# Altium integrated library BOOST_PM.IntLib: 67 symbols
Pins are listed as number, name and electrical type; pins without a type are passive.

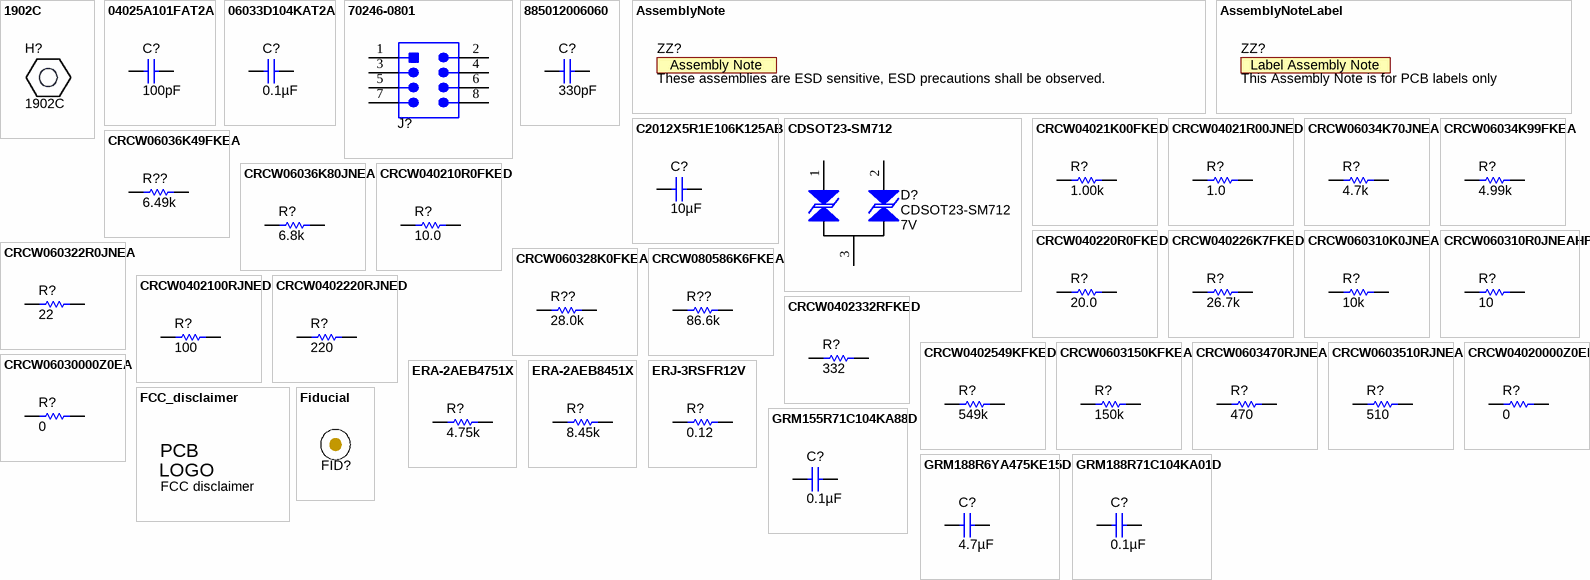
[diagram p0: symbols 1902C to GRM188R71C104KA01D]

## 1902C
designator H?
Standoff, Hex, 0.5"L #4-40 Nylon; Manufacturer: Keystone; CompType: Hardware
footprint Keystone_1902C

## 04025A101FAT2A
designator C?  ValueDisplayed: 100pF  (hidden comment: 04025A101FAT2A)
CAP, CERM, 100 pF, 50 V, +/- 1%, C0G/NP0, 0402; Manufacturer: AVX; Polarized: N; CompType: Capacitor; Value: 100pF; U/M: EA; Cap_F: 0.0000000001; Tolerance_%: 1; Value1: Unknown; VDC_V: 50; Value2: 50V; TaMin_C: -55; TaMax_C: 125; Cap_Case: 0402; SizeArea_mm2: 0.5; SizeAreaWB_mm2: 3; SizeZ_mm: 0.6; AEC Category: Q200
signal-integrity model Cap
simulation model Cap
footprint 0402
footprint 0402M
footprint 0402L
footprint 0402S
pins: 1, 2

## 06033D104KAT2A
designator C?  ValueDisplayed: 0.1µF  (hidden comment: 06033D104KAT2A)
CAP, CERM, 0.1uF, 25V, +/-10%, X5R, 0603; Manufacturer: AVX; Polarized: N; CompType: Capacitor; U/M: EA; Cap_F: 0.0000001; Tolerance_%: 10; ESR_Ohm: 0.048; Value1: 0.048 ohm; VDC_V: 25; IRMS_A: 0.53; TaMin_C: -55; TaMax_C: 85; Cap_Case: 0603
signal-integrity model Cap
simulation model Cap
footprint 0603
footprint 0603M
footprint 0603L
footprint 0603_HV
footprint 0603S
pins: 1, 2

## 70246-0801
designator J?  (value not drawn)
Header(shrouded), 2.54mm, 4x2, Gold, TH; Manufacturer: Molex; SymbolCreator: a0411947; Pitch_mm: 2.54; Gender: Male; Shrouded: Y; Row_Count: 2; Current_A: 2.5; Voltage_V: 250
footprint Molex_70246-0801
pins: 1, 2, 3, 4, 5, 6, 7, 8

## 885012006060
designator C?  ValueDisplayed: 330pF  (hidden comment: 885012006060)
CAP, CERM, 330 pF, 50 V, +/- 5%, C0G/NP0, 0603; Manufacturer: Wurth Elektronik; Polarized: N; CompType: Capacitor; Value: 330pF; U/M: EA; Cap_F: 0.00000000033; Tolerance_%: 5; Value1: Unknown; VDC_V: 50; Value2: 50V; TaMin_C: -55; TaMax_C: 125; Cap_Case: 0603; SizeArea_mm2: 1.28; SizeAreaWB_mm2: 4.68; SizeX_mm: 1.6; SizeY_mm: 0.8; SizeZ_mm: 1; AEC Category: Q200
signal-integrity model Cap
simulation model Cap
footprint 0603
footprint 0603M
footprint 0603L
footprint 0603_HV
footprint 0603S
pins: 1, 2

## AssemblyNote
designator ZZ?, comment These assemblies are ESD sensitive, ESD precautions shall be observed.  (no BOM)
SymbolCreator: codlsc; CompType: AssemblyNote
footprint AssemblyNote

## AssemblyNoteLabel
designator ZZ?, comment This Assembly Note is for PCB labels only  (no BOM)
SymbolCreator: a0412235
footprint AssemblyNoteLabel

## C2012X5R1E106K125AB
designator C?  ValueDisplayed: 10µF  (hidden comment: C2012X5R1E106K125AB)
CAP, CERM, 10uF, 25V, +/-10%, X5R, 0805; Manufacturer: TDK; Polarized: N; CompType: Capacitor; U/M: EA; Cap_F: 0.00001; Tolerance_%: 10; Value1: Unknown; VDC_V: 25; TaMin_C: -55; TaMax_C: 85; Cap_Case: 0805
signal-integrity model Cap
simulation model Cap
footprint 0805_HV
footprint 0805
footprint 0805M
footprint 0805L
pins: 1, 2

## CDSOT23-SM712
designator D?  value 7V
Diode, TVS, Bi, 7 V, 400 W, SOT-23; Manufacturer: Bourns; SymbolCreator: a0411947; U/M: EA; Power_W: 400; Vr_V: 7; Value1: 400W; SizeAreaWB_mm2: 14; SizeArea_mm2: 7.5; SizeX_mm: 2.5; SizeY_mm: 3; SizeZ_mm: 1.1; AEC Category: Q101
footprint SOT-23
footprint SOT-23M
footprint SOT-23L
pins: 1, 2, 3

## CRCW04021K00FKED
designator R?  ValueDisplayed: 1.00k  (hidden comment: CRCW04021K00FKED)
RES, 1.00 k, 1%, 0.063 W, 0402; Manufacturer: Vishay-Dale; CompType: Resistor; Value: 1.00k; Res_ohm: 1000; Value_Code: 1k00; Tolerance_%: 1; Power_W: 0.063; Value2: 0.063W; VDC_V: 50; TempCo: 100 ppm/C; EIA_Code: E96; U/M: EA
signal-integrity model Resistor
simulation model Resistor
footprint 0402
footprint 0402M
footprint 0402L
footprint 0402S
pins: 1, 2

## CRCW04021R00JNED
designator R?  ValueDisplayed: 1.0  (hidden comment: CRCW04021R00JNED)
RES, 1.0, 5%, 0.063 W, 0402; Manufacturer: Vishay-Dale; CompType: Resistor; Value: 1.0; Res_ohm: 1; Value_Code: 1R00; Tolerance_%: 5; Power_W: 0.063; Value2: 0.063W; VDC_V: 50; TempCo: 200 ppm/C; EIA_Code: E24; U/M: EA
signal-integrity model Resistor
simulation model Resistor
footprint 0402
footprint 0402M
footprint 0402L
footprint 0402S
pins: 1, 2

## CRCW06034K70JNEA
designator R?  value 4.7k  (hidden comment: CRCW06034K70JNEA)
RES, 4.7k ohm, 5%, 0.1W, 0603; Manufacturer: Vishay-Dale; CompType: Resistor; Res_ohm: 4700; Value_Code: 4k70; Tolerance_%: 5; Power_W: 0.1; VDC_V: 75; TempCo: 200 ppm/C; EIA_Code: E24; U/M: EA
signal-integrity model Resistor
simulation model Resistor
footprint 0603
footprint 0603M
footprint 0603L
footprint 0603_HV
footprint 0603S
pins: 1, 2

## CRCW06034K99FKEA
designator R?  value 4.99k  (hidden comment: CRCW06034K99FKEA)
RES, 4.99k ohm, 1%, 0.1W, 0603; Manufacturer: Vishay-Dale; CompType: Resistor; Res_ohm: 4990; Value_Code: 4k99; Tolerance_%: 1; Power_W: 0.1; VDC_V: 75; TempCo: 100 ppm/C; EIA_Code: E96; U/M: EA
signal-integrity model Resistor
simulation model Resistor
footprint 0603
footprint 0603M
footprint 0603L
footprint 0603_HV
footprint 0603S
pins: 1, 2

## CRCW06036K49FKEA
designator R??  ValueDisplayed: 6.49k  (hidden comment: CRCW06036K49FKEA)
RES, 6.49 k, 1%, 0.1 W, 0603; Manufacturer: Vishay-Dale; CompType: Resistor; Value: 6.49k; Res_ohm: 6490; Value_Code: 6k49; Tolerance_%: 1; Power_W: 0.1; Value2: 0.1W; VDC_V: 75; TempCo: 100 ppm/C; SizeArea_mm2: 1.28; SizeX_mm: 1.6; SizeY_mm: 0.8; EIA_Code: E96; U/M: EA; AEC Category: Q200
signal-integrity model Resistor
simulation model Resistor
footprint 0603
footprint 0603M
footprint 0603L
footprint 0603_HV
footprint 0603S
pins: 1, 2

## CRCW06036K80JNEA
designator R?  value 6.8k  (hidden comment: CRCW06036K80JNEA)
RES, 6.8k ohm, 5%, 0.1W, 0603; Manufacturer: Vishay-Dale; CompType: Resistor; Res_ohm: 6800; Value_Code: 6k80; Tolerance_%: 5; Power_W: 0.1; VDC_V: 75; TempCo: 200 ppm/C; EIA_Code: E24; U/M: EA
signal-integrity model Resistor
simulation model Resistor
footprint 0603
footprint 0603M
footprint 0603L
footprint 0603_HV
footprint 0603S
pins: 1, 2

## CRCW040210R0FKED
designator R?  ValueDisplayed: 10.0  (hidden comment: CRCW040210R0FKED)
RES, 10.0, 1%, 0.063 W, 0402; Manufacturer: Vishay-Dale; CompType: Resistor; Value: 10.0; Res_ohm: 10; Value_Code: 10R0; Tolerance_%: 1; Power_W: 0.063; Value2: 0.063W; VDC_V: 50; TempCo: 100 ppm/C; EIA_Code: E96; U/M: EA
signal-integrity model Resistor
simulation model Resistor
footprint 0402
footprint 0402M
footprint 0402L
footprint 0402S
pins: 1, 2

## CRCW040220R0FKED
designator R?  ValueDisplayed: 20.0  (hidden comment: CRCW040220R0FKED)
RES, 20.0, 1%, 0.063 W, 0402; Manufacturer: Vishay-Dale; CompType: Resistor; Value: 20.0; Res_ohm: 20; Value_Code: 20R0; Tolerance_%: 1; Power_W: 0.063; Value2: 0.063W; VDC_V: 50; TempCo: 100 ppm/C; EIA_Code: E96; U/M: EA
signal-integrity model Resistor
simulation model Resistor
footprint 0402
footprint 0402M
footprint 0402L
footprint 0402S
pins: 1, 2

## CRCW040226K7FKED
designator R?  ValueDisplayed: 26.7k  (hidden comment: CRCW040226K7FKED)
RES, 26.7 k, 1%, 0.063 W, 0402; Manufacturer: Vishay-Dale; CompType: Resistor; Value: 26.7k; Res_ohm: 26700; Value_Code: 26k7; Tolerance_%: 1; Power_W: 0.063; Value2: 0.063W; VDC_V: 50; TempCo: 100 ppm/C; EIA_Code: E96; U/M: EA
signal-integrity model Resistor
simulation model Resistor
footprint 0402
footprint 0402M
footprint 0402L
footprint 0402S
pins: 1, 2

## CRCW060310K0JNEA
designator R?  value 10k  (hidden comment: CRCW060310K0JNEA)
RES, 10k ohm, 5%, 0.1W, 0603; Manufacturer: Vishay-Dale; CompType: Resistor; Res_ohm: 10000; Value_Code: 10k0; Tolerance_%: 5; Power_W: 0.1; VDC_V: 75; TempCo: 200 ppm/C; EIA_Code: E24; U/M: EA
signal-integrity model Resistor
simulation model Resistor
footprint 0603
footprint 0603M
footprint 0603L
footprint 0603_HV
footprint 0603S
pins: 1, 2

## CRCW060310R0JNEAHP
designator R?  value 10  (hidden comment: CRCW060310R0JNEAHP)
RES, 10 ohm, 5%, 0.25W, 0603; Manufacturer: Vishay-Dale; CompType: Resistor; Value_Code: 10R0; Tolerance_%: 5; Power_W: 0.25; VDC_V: 75; TempCo: 200 ppm/C; EIA_Code: E24; U/M: EA
signal-integrity model Resistor
simulation model Resistor
footprint 0603
footprint 0603M
footprint 0603L
footprint 0603_HV
footprint 0603S
pins: 1, 2

## CRCW060322R0JNEA
designator R?  value 22  (hidden comment: CRCW060322R0JNEA)
RES, 22 ohm, 5%, 0.1W, 0603; Manufacturer: Vishay-Dale; CompType: Resistor; Value_Code: 22R0; Tolerance_%: 5; Power_W: 0.1; VDC_V: 75; TempCo: 200 ppm/C; EIA_Code: E24; U/M: EA
signal-integrity model Resistor
simulation model Resistor
footprint 0603
footprint 0603M
footprint 0603L
footprint 0603_HV
footprint 0603S
pins: 1, 2

## CRCW060328K0FKEA
designator R??  ValueDisplayed: 28.0k  (hidden comment: CRCW060328K0FKEA)
RES, 28.0 k, 1%, 0.1 W, 0603; Manufacturer: Vishay-Dale; CompType: Resistor; Value: 28.0k; Res_ohm: 28000; Value_Code: 28k0; Tolerance_%: 1; Power_W: 0.1; Value2: 0.1W; VDC_V: 75; TempCo: 100 ppm/C; SizeArea_mm2: 1.28; SizeX_mm: 1.6; SizeY_mm: 0.8; EIA_Code: E96; U/M: EA; AEC Category: Q200
signal-integrity model Resistor
simulation model Resistor
footprint 0603
footprint 0603M
footprint 0603L
footprint 0603_HV
footprint 0603S
pins: 1, 2

## CRCW080586K6FKEA
designator R??  ValueDisplayed: 86.6k  (hidden comment: CRCW080586K6FKEA)
RES, 86.6 k, 1%, 0.125 W, 0805; Manufacturer: Vishay-Dale; CompType: Resistor; Value: 86.6k; Res_ohm: 86600; Value_Code: 86k6; Tolerance_%: 1; Power_W: 0.125; Value2: 0.125W; VDC_V: 150; TempCo: 100 ppm/C; SizeArea_mm2: 2.5; SizeX_mm: 2; SizeY_mm: 1.25; SizeZ_mm: 1.45; EIA_Code: E96; U/M: EA; AEC Category: Q200
signal-integrity model Resistor
simulation model Resistor
footprint 0805_HV
footprint 0805_HV1
footprint 0805
footprint 0805M
footprint 0805L
pins: 1, 2

## CRCW0402100RJNED
designator R?  ValueDisplayed: 100  (hidden comment: CRCW0402100RJNED)
RES, 100, 5%, 0.063 W, 0402; Manufacturer: Vishay-Dale; CompType: Resistor; Value: 100; Value_Code: 100R; Tolerance_%: 5; Power_W: 0.063; Value2: 0.063W; VDC_V: 50; TempCo: 200 ppm/C; EIA_Code: E24; U/M: EA
signal-integrity model Resistor
simulation model Resistor
footprint 0402
footprint 0402M
footprint 0402L
footprint 0402S
pins: 1, 2

## CRCW0402220RJNED
designator R?  ValueDisplayed: 220  (hidden comment: CRCW0402220RJNED)
RES, 220, 5%, 0.063 W, 0402; Manufacturer: Vishay-Dale; CompType: Resistor; Value: 220; Value_Code: 220R; Tolerance_%: 5; Power_W: 0.063; Value2: 0.063W; VDC_V: 50; TempCo: 200 ppm/C; EIA_Code: E24; U/M: EA
signal-integrity model Resistor
simulation model Resistor
footprint 0402
footprint 0402M
footprint 0402L
footprint 0402S
pins: 1, 2

## CRCW0402332RFKED
designator R?  ValueDisplayed: 332  (hidden comment: CRCW0402332RFKED)
RES, 332, 1%, 0.063 W, 0402; Manufacturer: Vishay-Dale; CompType: Resistor; Value: 332; Value_Code: 332R; Tolerance_%: 1; Power_W: 0.063; Value2: 0.063W; VDC_V: 50; TempCo: 100 ppm/C; EIA_Code: E96; U/M: EA
signal-integrity model Resistor
simulation model Resistor
footprint 0402
footprint 0402M
footprint 0402L
footprint 0402S
pins: 1, 2

## CRCW0402549KFKED
designator R?  ValueDisplayed: 549k  (hidden comment: CRCW0402549KFKED)
RES, 549 k, 1%, 0.063 W, 0402; Manufacturer: Vishay-Dale; CompType: Resistor; Value: 549k; Res_ohm: 549000; Tolerance_%: 1; Power_W: 0.063; Value2: 0.063W; VDC_V: 50; TempCo: 100 ppm/C; EIA_Code: E96; U/M: EA
signal-integrity model Resistor
simulation model Resistor
footprint 0402
footprint 0402M
footprint 0402L
footprint 0402S
pins: 1, 2

## CRCW0603150KFKEA
designator R?  ValueDisplayed: 150k  (hidden comment: CRCW0603150KFKEA)
RES, 150 k, 1%, 0.1 W, 0603; Manufacturer: Vishay-Dale; CompType: Resistor; Value: 150k; Res_ohm: 150000; Tolerance_%: 1; Power_W: 0.1; Value2: 0.1W; VDC_V: 75; TempCo: 100 ppm/C; SizeArea_mm2: 1.28; SizeX_mm: 1.6; SizeY_mm: 0.8; EIA_Code: E96; U/M: EA; AEC Category: Q200
signal-integrity model Resistor
simulation model Resistor
footprint 0603
footprint 0603M
footprint 0603L
footprint 0603_HV
footprint 0603S
pins: 1, 2

## CRCW0603470RJNEA
designator R?  value 470  (hidden comment: CRCW0603470RJNEA)
RES, 470 ohm, 5%, 0.1W, 0603; Manufacturer: Vishay-Dale; CompType: Resistor; Value_Code: 470R; Tolerance_%: 5; Power_W: 0.1; VDC_V: 75; TempCo: 200 ppm/C; EIA_Code: E24; U/M: EA
signal-integrity model Resistor
simulation model Resistor
footprint 0603
footprint 0603M
footprint 0603L
footprint 0603_HV
footprint 0603S
pins: 1, 2

## CRCW0603510RJNEA
designator R?  value 510  (hidden comment: CRCW0603510RJNEA)
RES, 510 ohm, 5%, 0.1W, 0603; Manufacturer: Vishay-Dale; CompType: Resistor; Value_Code: 510R; Tolerance_%: 5; Power_W: 0.1; VDC_V: 75; TempCo: 200 ppm/C; EIA_Code: E24; U/M: EA
signal-integrity model Resistor
simulation model Resistor
footprint 0603
footprint 0603M
footprint 0603L
footprint 0603_HV
footprint 0603S
pins: 1, 2

## CRCW04020000Z0ED
designator R?  ValueDisplayed: 0  (hidden comment: CRCW04020000Z0ED)
RES, 0, 5%, 0.063 W, 0402; Manufacturer: Vishay-Dale; CompType: Resistor; Value: 0; Value_Code: 0000; Tolerance_%: 5; Power_W: 0.063; Value2: 0.063W; VDC_V: 50; TempCo: 200 ppm/C; EIA_Code: E24; U/M: EA
signal-integrity model Resistor
simulation model Resistor
footprint 0402
footprint 0402M
footprint 0402L
footprint 0402S
pins: 1, 2

## CRCW06030000Z0EA
designator R?  ValueDisplayed: 0  (hidden comment: CRCW06030000Z0EA)
RES, 0, 5%, 0.1 W, 0603; Manufacturer: Vishay-Dale; CompType: Resistor; Value: 0; Value_Code: 0000; Tolerance_%: 5; Power_W: 0.1; Value2: 0.1W; VDC_V: 75; TempCo: 200 ppm/C; SizeArea_mm2: 1.28; SizeX_mm: 1.6; SizeY_mm: 0.8; SizeZ_mm: 1; EIA_Code: E24; U/M: EA; AEC Category: Q200
signal-integrity model Resistor
simulation model Resistor
footprint 0603
footprint 0603M
footprint 0603L
footprint 0603_HV
footprint 0603S
pins: 1, 2

## ERA-2AEB4751X
designator R?  ValueDisplayed: 4.75k  (hidden comment: ERA-2AEB4751X)
RES, 4.75 k, 0.1%, 0.063 W, 0402; Manufacturer: Panasonic; CompType: Resistor; Value: 4.75k; Res_ohm: 4750; Value_Code: 4k75; Tolerance_%: 0.1; Power_W: 0.063; Value2: 0.063W; VDC_V: 50; TempCo: 25 ppm/C; EIA_Code: E192; U/M: EA
signal-integrity model Resistor
simulation model Resistor
footprint 0402
footprint 0402M
footprint 0402L
footprint 0402S
pins: 1, 2

## ERA-2AEB8451X
designator R?  ValueDisplayed: 8.45k  (hidden comment: ERA-2AEB8451X)
RES, 8.45 k, 0.1%, 0.063 W, 0402; Manufacturer: Panasonic; CompType: Resistor; Value: 8.45k; Res_ohm: 8450; Value_Code: 8k45; Tolerance_%: 0.1; Power_W: 0.063; Value2: 0.063W; VDC_V: 50; TempCo: 25 ppm/C; EIA_Code: E192; U/M: EA
signal-integrity model Resistor
simulation model Resistor
footprint 0402
footprint 0402M
footprint 0402L
footprint 0402S
pins: 1, 2

## ERJ-3RSFR12V
designator R?  value 0.12  (hidden comment: ERJ-3RSFR12V)
RES, 0.12 ohm, 1%, 0.1W, 0603; Manufacturer: Panasonic; CompType: Resistor; Value_Code: R120; Tolerance_%: 1; Power_W: 0.1; TempCo: 300 ppm/C; EIA_Code: E96; U/M: EA
signal-integrity model Resistor
simulation model Resistor
footprint 0603
footprint 0603M
footprint 0603L
footprint 0603_HV
footprint 0603S
pins: 1, 2

## FCC_disclaimer
designator Logo?, comment FCC disclaimer  (no BOM)
FCC_disclaimer; SymbolCreator: codlsc
footprint FCC_disclaimer
footprint FCC_disclaimer_stacked

## Fiducial
designator FID?  (value not drawn)
Fiducial mark.  There is nothing to buy or mount.; SymbolCreator: codlsc
footprint Fiducial10-30
footprint Fiducial10-20
footprint Fiducial15-30
footprint Fiducial20-40
footprint Fiducial6.4-20

## GRM155R71C104KA88D
designator C?  ValueDisplayed: 0.1µF  (hidden comment: GRM155R71C104KA88D)
CAP, CERM, 0.1 µF, 16 V, +/- 10%, X7R, 0402; Manufacturer: MuRata; Polarized: N; CompType: Capacitor; Value: 0.1uF; U/M: EA; Cap_F: 0.0000001; Tolerance_%: 10; Value1: Unknown; VDC_V: 16; Value2: 16V; TaMin_C: -55; TaMax_C: 125; Cap_Case: 0402
signal-integrity model Cap
simulation model Cap
footprint 0402
footprint 0402M
footprint 0402L
footprint 0402S
pins: 1, 2

## GRM188R6YA475KE15D
designator C?  ValueDisplayed: 4.7µF  (hidden comment: GRM188R6YA475KE15D)
CAP, CERM, 4.7 µF, 35 V, +/- 10%, X5R, 0603; Manufacturer: MuRata; Polarized: N; CompType: Capacitor; Value: 4.7uF; U/M: EA; Cap_F: 0.0000047; Tolerance_%: 10; Value1: Unknown; VDC_V: 35; Value2: 35V; TaMin_C: -55; TaMax_C: 85; Cap_Case: 0603; SizeArea_mm2: 1.28; SizeAreaWB_mm2: 4.68; SizeX_mm: 1.6; SizeY_mm: 0.8; SizeZ_mm: 1; AEC Category: Q200
signal-integrity model Cap
simulation model Cap
footprint 0603
footprint 0603M
footprint 0603L
footprint 0603_HV
footprint 0603S
pins: 1, 2

## GRM188R71C104KA01D
designator C?  ValueDisplayed: 0.1µF  (hidden comment: GRM188R71C104KA01D)
CAP, CERM, 0.1 µF, 16 V, +/- 10%, X7R, 0603; Manufacturer: MuRata; Polarized: N; CompType: Capacitor; Value: 0.1uF; U/M: EA; Cap_F: 0.0000001; Tolerance_%: 10; Value1: Unknown; VDC_V: 16; Value2: 16V; TaMin_C: -55; TaMax_C: 125; Cap_Case: 0603; SizeArea_mm2: 1.28; SizeAreaWB_mm2: 4.68; SizeX_mm: 1.6; SizeY_mm: 0.8; SizeZ_mm: 1; AEC Category: Q200
signal-integrity model Cap
simulation model Cap
footprint 0603
footprint 0603M
footprint 0603L
footprint 0603_HV
footprint 0603S
pins: 1, 2

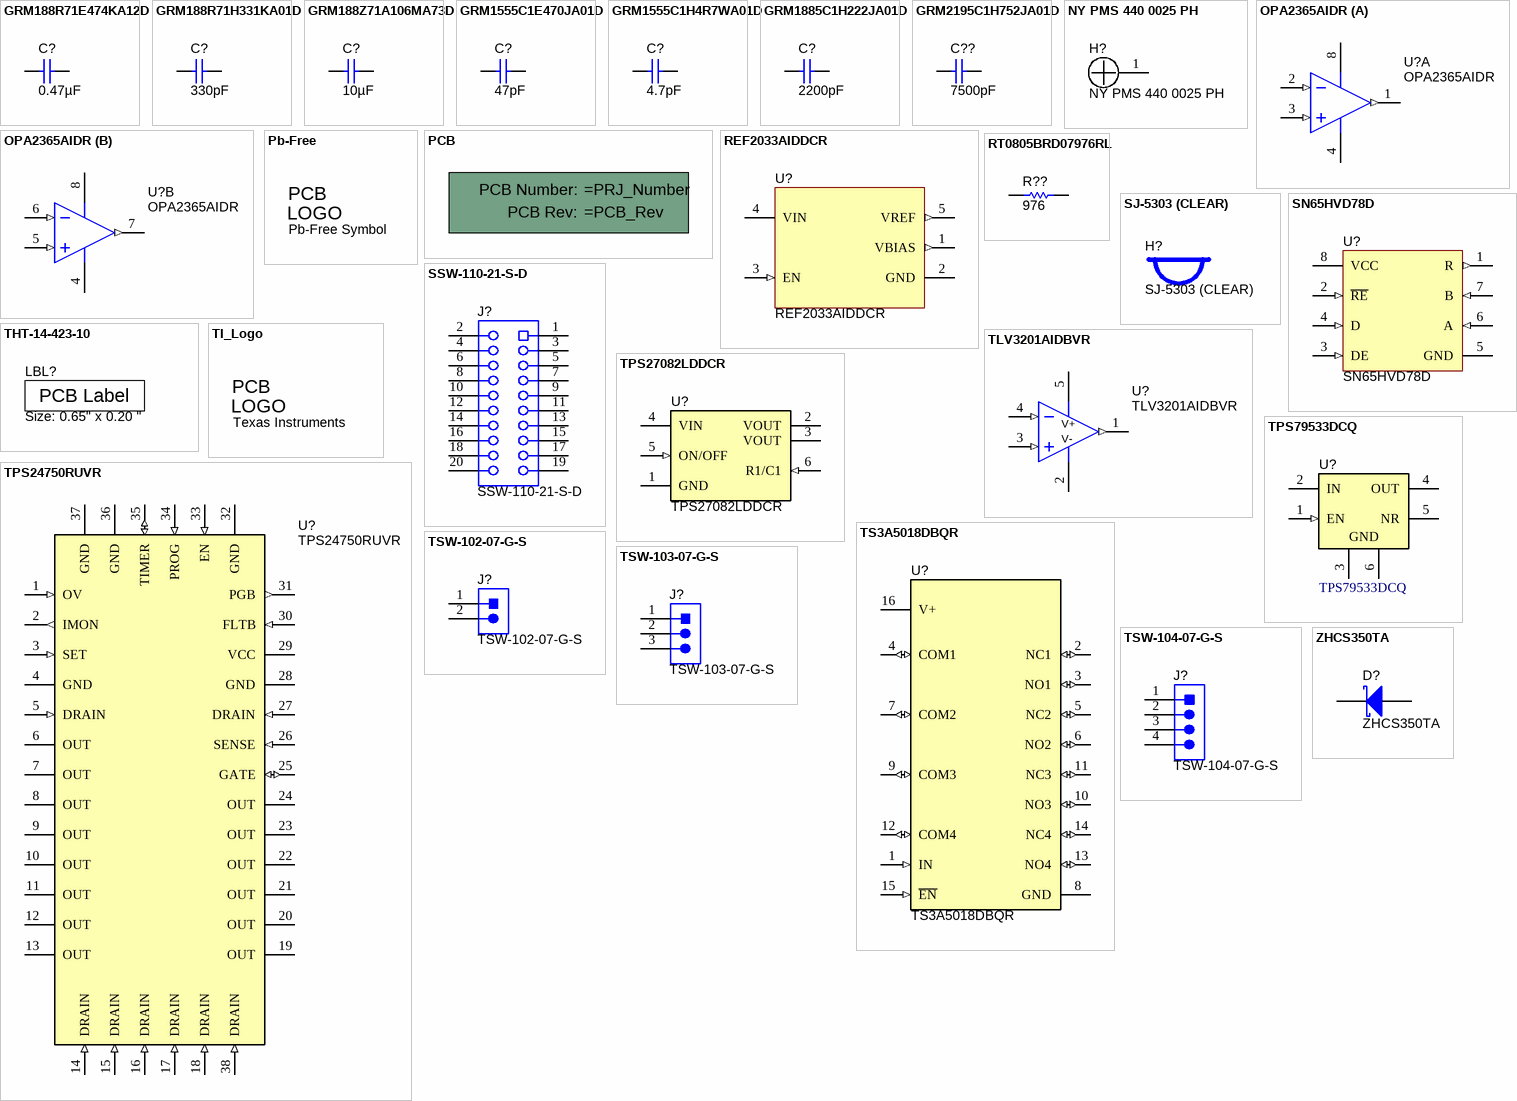
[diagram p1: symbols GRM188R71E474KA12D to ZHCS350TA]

## GRM188R71E474KA12D
designator C?  ValueDisplayed: 0.47µF  (hidden comment: GRM188R71E474KA12D)
CAP, CERM, 0.47 µF, 25 V, +/- 10%, X7R, 0603; Manufacturer: MuRata; Polarized: N; CompType: Capacitor; Value: 0.47uF; U/M: EA; Cap_F: 0.00000047; Tolerance_%: 10; Value1: Unknown; VDC_V: 25; Value2: 25V; TaMin_C: -55; TaMax_C: 125; Cap_Case: 0603; SizeArea_mm2: 1.28; SizeAreaWB_mm2: 4.68; SizeX_mm: 1.6; SizeY_mm: 0.8; SizeZ_mm: 1; AEC Category: Q200
signal-integrity model Cap
simulation model Cap
footprint 0603
footprint 0603M
footprint 0603L
footprint 0603_HV
footprint 0603S
pins: 1, 2

## GRM188R71H331KA01D
designator C?  ValueDisplayed: 330pF  (hidden comment: GRM188R71H331KA01D)
CAP, CERM, 330pF, 50V, +/-10%, X7R, 0603; Manufacturer: MuRata; Polarized: N; CompType: Capacitor; U/M: EA; Cap_F: 0.00000000033; Tolerance_%: 10; Value1: Unknown; VDC_V: 50; TaMin_C: -55; TaMax_C: 125; Cap_Case: 0603
signal-integrity model Cap
simulation model Cap
footprint 0603
footprint 0603M
footprint 0603L
footprint 0603_HV
footprint 0603S
pins: 1, 2

## GRM188Z71A106MA73D
designator C?  ValueDisplayed: 10µF  (hidden comment: GRM188Z71A106MA73D)
CAP, CERM, 10 µF, 10 V, +/- 20%, X7R, 0603; Manufacturer: MuRata; Polarized: N; CompType: Capacitor; Value: 10uF; U/M: EA; Cap_F: 0.00001; Tolerance_%: 20; Value1: Unknown; VDC_V: 10; Value2: 10V; TaMin_C: -55; TaMax_C: 125; Cap_Case: 0603; SizeArea_mm2: 1.28; SizeAreaWB_mm2: 4.68; SizeX_mm: 1.6; SizeY_mm: 0.8; SizeZ_mm: 1; AEC Category: Q200
signal-integrity model Cap
simulation model Cap
footprint 0603
footprint 0603M
footprint 0603L
footprint 0603_HV
footprint 0603S
pins: 1, 2

## GRM1555C1E470JA01D
designator C?  ValueDisplayed: 47pF  (hidden comment: GRM1555C1E470JA01D)
CAP, CERM, 47 pF, 25 V, +/- 5%, C0G/NP0, 0402; Manufacturer: MuRata; Polarized: N; CompType: Capacitor; Value: 47pF; U/M: EA; Cap_F: 0.000000000047; Tolerance_%: 5; Value1: Unknown; VDC_V: 25; Value2: 25V; TaMin_C: -55; TaMax_C: 125; Cap_Case: 0402
signal-integrity model Cap
simulation model Cap
footprint 0402
footprint 0402M
footprint 0402L
footprint 0402S
pins: 1, 2

## GRM1555C1H4R7WA01D
designator C?  ValueDisplayed: 4.7pF  (hidden comment: GRM1555C1H4R7WA01D)
CAP, CERM, 4.7 pF, 50 V, +/- 1%, C0G/NP0, 0402; Manufacturer: MuRata; Polarized: N; CompType: Capacitor; Value: 4.7pF; U/M: EA; Cap_F: 0.0000000000047; Tolerance_%: 1; Value1: Unknown; VDC_V: 50; Value2: 50V; TaMin_C: -55; TaMax_C: 125; Cap_Case: 0402
signal-integrity model Cap
simulation model Cap
footprint 0402
footprint 0402M
footprint 0402L
footprint 0402S
pins: 1, 2

## GRM1885C1H222JA01D
designator C?  ValueDisplayed: 2200pF  (hidden comment: GRM1885C1H222JA01D)
CAP, CERM, 2200 pF, 50 V, +/- 5%, C0G/NP0, 0603; Manufacturer: MuRata; Polarized: N; CompType: Capacitor; Value: 2200pF; U/M: EA; Cap_F: 0.0000000022; Tolerance_%: 5; Value1: Unknown; VDC_V: 50; Value2: 50V; TaMin_C: -55; TaMax_C: 125; Cap_Case: 0603
signal-integrity model Cap
simulation model Cap
footprint 0603
footprint 0603M
footprint 0603L
footprint 0603_HV
footprint 0603S
pins: 1, 2

## GRM2195C1H752JA01D
designator C??  ValueDisplayed: 7500pF  (hidden comment: GRM2195C1H752JA01D)
CAP, CERM, 7500 pF, 50 V, +/- 5%, C0G/NP0, 0805; Manufacturer: MuRata; Polarized: N; CompType: Capacitor; Value: 7500pF; U/M: EA; Cap_F: 0.0000000075; Tolerance_%: 5; Value1: Unknown; VDC_V: 50; Value2: 50V; TaMin_C: -55; TaMax_C: 125; Cap_Case: 0805; SizeArea_mm2: 2.5; SizeAreaWB_mm2: 6.75; SizeX_mm: 2; SizeY_mm: 1.25; SizeZ_mm: 1.45; AEC Category: Q200
signal-integrity model Cap
simulation model Cap
footprint 0805_HV
footprint 0805_HV1
footprint 0805
footprint 0805M
footprint 0805L
pins: 1, 2

## NY PMS 440 0025 PH
designator H?
Machine Screw, Round, #4-40 x 1/4, Nylon, Philips panhead; Manufacturer: B&F Fastener Supply; CompType: Hardware; SymbolCreator: codlsc; U/M: EA
footprint NY PMS 440 0025 PH
footprint NY PMS 440 0025 PH_3Donly
pins: 1

## OPA2365AIDR
designator U?
50 MHz, Low-Noise Single-Supply Rail-to-Rail Operational Amplifier, 2.2 to 5.5 V, -40 to 125 degC, 8-pin SOIC (D0008A), Green (RoHS & no Sb/Br); Manufacturer: Texas Instruments; Alternate Manufacturer: None; Alternate PartNumber: Equivalent; CMRR(Min)(dB): 100; IIB(Max)(pA): 10; Iq per channel(Max)(mA): 5; Number of Channels: 2; Offset Drift(Typ)(uV/C): 1; Slew Rate(Typ)(V/us): 25; Sub Family: High Speed Amplifier (>=50MHz), Low Input Bias Current Amp (<=10pA), Low Offset Voltage Amplifier (<=500uV), Low Supply Voltage Amplifier (<=2.7V); Total Supply Voltage(Max)(+5V is 5, +/-5V is 10): 5.5; Total Supply Voltage(Min)(+5V is 5, +/-5V is 10): 2.2; Vio (25C)(Max)(mV): 0.2
footprint D0008A_N (SOIC, 8-Leads, Body 4.9x3.9mm, Pitch 1.27mm, IPC Medium Density)
footprint D0008A_L (SOIC, 8-Leads, Body 4.9x3.9mm, Pitch 1.27mm, IPC High Density)
footprint D0008A_M (SOIC, 8-Leads, Body 4.9x3.9mm, Pitch 1.27mm, IPC Low Density)
pins on every part: 4 V- (power), 8 V+ (power)
part A pins: 1 VOUT A (out), 2 IN A- (in), 3 IN A+ (in)
part B pins: 5 IN B+ (in), 6 IN B- (in), 7 VOUT B (out)

## Pb-Free
designator Logo?, comment Pb-Free Symbol  (no BOM)
SymbolCreator: a0412235
footprint Pb-Free_Overlay_Medium
footprint Pb-Free_Overlay_Small

## PCB
designator !PCB?, comment Printed Circuit Board  (value not drawn)  (mechanical)
Manufacturer: Any; SymbolCreator: a0412235; CompType: PCB
1 alternate drawing of the same symbol

## REF2033AIDDCR
designator U?
Low-Drift, Low-Power, Dual-Output, VREF and VREF / 2 Voltage References, DDC0005A; Alternate PartNumber: REF2033AIDDCT; Manufacturer: Texas Instruments; SymbolCreator: a0799628; CompType: IC; U/M: EA
footprint DDC0005A_N
footprint DDC0005A_M
footprint DDC0005A_L
pins: 1 VBIAS (out), 2 GND (power), 3 EN (in), 4 VIN (power), 5 VREF (out)

## RT0805BRD07976RL
designator R??  ValueDisplayed: 976  (hidden comment: RT0805BRD07976RL)
RES, 976, 0.1%, 0.125 W, 0805; Manufacturer: Yageo America; CompType: Resistor; Value: 976; Value_Code: 976R; Tolerance_%: 0.1; Power_W: 0.125; Value2: 0.125W; VDC_V: 150; TempCo: 25 ppm/C; SizeArea_mm2: 2.5; SizeX_mm: 2; SizeY_mm: 1.25; SizeZ_mm: 1.45; EIA_Code: E192; U/M: EA; AEC Category: Q200
signal-integrity model Resistor
simulation model Resistor
footprint 0805_HV
footprint 0805_HV1
footprint 0805
footprint 0805M
footprint 0805L
pins: 1, 2

## SJ-5303 (CLEAR)
designator H?
Bumpon, Hemisphere, 0.44 X 0.20, Clear; Manufacturer: 3M; SymbolCreator: a0412235
footprint Bumpon_SJ5003Transparent

## SN65HVD78D
designator U?
3.3V-Supply RS-485 with IEC ESD Protection, D0008A; Alternate Manufacturer: None; Manufacturer: Texas Instruments; SymbolCreator: a0411947; CompType: IC; U/M: EA
footprint D0008A_N
footprint D0008A_M
footprint D0008A_L
pins: 1 R (out), 2 ~{RE} (in), 3 DE (in), 4 D (in), 5 GND (power), 6 A (in), 7 B (in), 8 VCC (power)
1 alternate drawing of the same symbol

## SSW-110-21-S-D
designator J?
Receptacle, 2.54mm, 10x2, Gold, TH; Manufacturer: Samtec; SymbolCreator: a0412235; Pitch_mm: 2.54; Gender: Female; Row_Count: 2
footprint Samtec_SSW-110-x1-x-D
pins: 1, 2, 3, 4, 5, 6, 7, 8, 9, 10, 11, 12, 13, 14, 15, 16, 17, 18, 19, 20

## THT-14-423-10
designator LBL?, comment Size: 0.65" x 0.20 "
Thermal Transfer Printable Labels, 0.650" W x 0.200" H - 10,000 per roll; Manufacturer: Brady; PartNumber: THT-14-423-10; SymbolCreator: a0412235; CompType: Label
footprint Label_650x200

## TI_Logo
designator Logo?, comment Texas Instruments  (no BOM)
Texas Instrument Corporate Signature; SymbolCreator: codlsc
footprint TI_Stacked_SolderMask_Medium
footprint TI_Stacked_SolderMask_Small
footprint TI_Stacked_Overlay_Medium
footprint TI_Stacked_Overlay_Small
footprint TI_Horizontal_SolderMask_Medium
footprint TI_Horizontal_SolderMask_Small
footprint TI_Horizontal_Overlay_Medium
footprint TI_Horizontal_Overlay_Small
footprint TI_Symbol_SolderMask_Small
footprint TI_Symbol_Overlay_Medium
footprint TI_Symbol_Overlay_Small
footprint TI_Symbol_SolderMask_Medium

## TLV3201AIDBVR
designator U?
40-ns, microPOWER, Push-Pull Output Comparators, DBV0005A; Alternate PartNumber: TLV3201AIDBVT; Manufacturer: Texas Instruments; SizeArea_mm2: 8.12; SizeAreaWB_mm2: 14.82; SizeX_mm: 2.8; SizeY_mm: 2.9; SizeZ_mm: 1.45; CompType: IC; U/M: EA
footprint DBV0005A_N
footprint DBV0005A_M
footprint DBV0005A_L
pins: 1 OUT (out), 2 V- (power), 3 IN+ (in), 4 IN- (in), 5 V+ (power)
1 alternate drawing of the same symbol

## TPS24750RUVR
designator U?
2.5 to 18 V Positive Voltage 10A Integrated Hot-Swap Controller, RUV0036A; Alternate PartNumber: TPS24750RUVT; Manufacturer: Texas Instruments; SymbolCreator: a0411947; SizeArea_mm2: 24.5; SizeAreaWB_mm2: 49.5; SizeX_mm: 3.5; SizeY_mm: 7; SizeZ_mm: 1; CompType: IC; U/M: EA
footprint RUV0036A
pins: 1 OV (in), 2 IMON (out), 3 SET (in), 4 GND (power), 5 DRAIN (in), 6 OUT (power), 7 OUT (power), 8 OUT (power), 9 OUT (power), 10 OUT (power), 11 OUT (power), 12 OUT (power), 13 OUT (power), 14 DRAIN (in), 15 DRAIN (in), 16 DRAIN (in), 17 DRAIN (in), 18 DRAIN (in), 19 OUT (power), 20 OUT (power), 21 OUT (power), 22 OUT (power), 23 OUT (power), 24 OUT (power), 25 GATE (io), 26 SENSE (in), 27 DRAIN (in), 28 GND (power), 29 VCC (power), 30 FLTB (in), 31 PGB (out), 32 GND (power), 33 EN (in), 34 PROG (in), 35 TIMER (io), 36 GND (power), 37 GND (power), 38 DRAIN (in)
1 alternate drawing of the same symbol

## TPS27082LDDCR
designator U?
1.2V - 8V, 3A PFET Load Switch with Configurable Slew Rate, Fast Transient Isolation and Hysteretic Control, DDC0006A; Manufacturer: Texas Instruments; SymbolCreator: a0411947; SizeArea_mm2: 4.8675; SizeAreaWB_mm2: 10.4675; SizeX_mm: 1.65; SizeY_mm: 2.95; SizeZ_mm: 0.87; CompType: IC; U/M: EA
footprint DDC0006A_N
footprint DDC0006A_M
footprint DDC0006A_L
pins: 1 GND (power), 2 VOUT (power), 3 VOUT (power), 4 VIN (power), 5 ON/OFF (in), 6 R1/C1 (in)
1 alternate drawing of the same symbol

## TPS79533DCQ
designator U?
Single Output High PSRR LDO, 500 mA, Fixed 3.3 V Output, 2.7 to 5.5 V Input, 6-pin SOT-223 (DCQ), Green (RoHS & no Sb/Br); Manufacturer: Texas Instruments; Alternate PartNumber: Equivalent; Accuracy(%): 2; Fixed Output Options(V): 3.3; Iout(Max)(A): 0.5; Iq(Typ)(mA): 0.26; Rating: Catalog; SubFamily: Single Channel LDO; Vdo(Typ)(mV): 105; Vin(Max)(V): 5.5; Vin(Min)(V): 2.7
footprint DCQ0006A_N (SOT223, 6-Leads, Body 6.5x3.5mm, Pitch 1.27mm, IPC Medium Density)
footprint DCQ0006A_L (SOT223, 6-Leads, Body 6.5x3.5mm, Pitch 1.27mm, IPC High Density)
footprint DCQ0006A_M (SOT223, 6-Leads, Body 6.5x3.5mm, Pitch 1.27mm, IPC Low Density)
pins: 1 EN (in) "The EN terminal is an input that enables or shuts down the device. When EN is a logic high, the device is enabled. When the device is a logic low, the device is in shutdown mode.", 2 IN (power) "Unregulated input to the device.", 3 GND (power) "Regulator ground", 4 OUT (power) "Regulator output", 5 NR "Connecting an external capacitor to this pin bypasses noise generated by the internal bandgap, which improves power-supply rejection and reduces output noise.", 6 GND (power) "Regulator ground"

## TS3A5018DBQR
designator U?
10-ohm Quad SPDT Analog Switch, DBQ0016A; Manufacturer: Texas Instruments; SymbolCreator: Altium; SizeArea_mm2: 60; SizeAreaWB_mm2: 96; SizeX_mm: 6; SizeY_mm: 10; SizeZ_mm: 1.75; CompType: IC; U/M: EA
footprint DBQ0016A_N
footprint DBQ0016A_M
footprint DBQ0016A_L
pins: 1 IN (in), 2 NC1 (io), 3 NO1 (io), 4 COM1 (io), 5 NC2 (io), 6 NO2 (io), 7 COM2 (io), 8 GND (power), 9 COM3 (io), 10 NO3 (io), 11 NC3 (io), 12 COM4 (io), 13 NO4 (io), 14 NC4 (io), 15 ~{EN} (in), 16 V+ (power)

## TSW-102-07-G-S
designator J?
Header, 100mil, 2x1, Gold, TH; Manufacturer: Samtec; SymbolCreator: a0412235; Pitch_mm: 2.54; Gender: Male; Shrouded: N; Row_Count: 1; Current_A: 6.3; Voltage_V: 550; Cert_CSA: Y
footprint TSW-102-07-G-S
footprint TSW-102-07-X-S
pins: 1, 2
1 alternate drawing of the same symbol

## TSW-103-07-G-S
designator J?
Header, 100mil, 3x1, Gold, TH; Manufacturer: Samtec; SymbolCreator: a0799628; Pitch_mm: 2.54; Gender: Male; Shrouded: N; Row_Count: 1; Current_A: 6.3; Voltage_V: 550; Cert_CSA: Y
footprint TSW-103-07-G-S
footprint TSW-103-07-X-S
pins: 1, 2, 3
3 alternate drawings of the same symbol

## TSW-104-07-G-S
designator J?
Header, 100mil, 4x1, Gold, TH; Manufacturer: Samtec; SymbolCreator: a0412235; Pitch_mm: 2.54; Gender: Male; Shrouded: N; Row_Count: 1; Current_A: 6.3; Voltage_V: 550; Cert_CSA: Y
footprint TSW-104-07-G-S
footprint TSW-104-07-X-S
pins: 1, 2, 3, 4

## ZHCS350TA
designator D?
Diode, Schottky, 40 V, 0.35 A, SOD-523; Manufacturer: Diodes Inc.; U/M: EA; Vf_V: 0.65; Value: 40V; Value1: 0.35A; Value2: 0.65V; Io_A: 0.35; Vr_V: 40
signal-integrity model Diode
simulation model ZHCS350
footprint SOD-523
pins: 1 K, 2 A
